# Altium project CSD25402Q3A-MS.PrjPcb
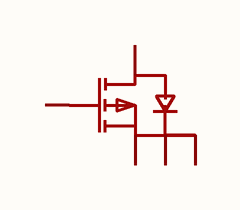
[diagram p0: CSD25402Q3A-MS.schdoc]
1 sheet, 1 parts. Net scope: global (net labels, ports and power ports of the same name join across sheets).

## Sheet CSD25402Q3A-MS.schdoc
size 127 x 101 mm

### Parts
Q?  csd25402q3a-ms  [DFN-8_L3.3-W3.3-P0.65-BL]  (value not drawn)

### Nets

Not connected (* = marked no-connect by the designer): Q? 1(S) 2(S) 3(S) 4(G) 5(D)

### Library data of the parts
Q? = csd25402q3a-ms: 数量:1个P沟道;漏源电压(Vdss):20V;连续漏极电流(Id):60A;导通电阻(RDS(on)):7mΩ@4.5V;耗散功率(Pd):22W;阈值电压(Vgs(th)):700mV;; Manufacturer: MSKSEMI(美森科); AddInBom: yes; ModelId: f0059a17dd8f409ba5a4c367eb8306e1; ModelTransform: 129.921,129.99974,0,0,0,0,0.002,31.498,0; Number: 1个P沟道; Drain to Source Voltage: 20V; Current - Continuous Drain(Id): 60A; Pd - Power Dissipation: 22W; Gate Threshold Voltage (Vgs(th)): 700mV; Gate Charge(Qg): 35nC; Input Capacitance(Ciss): 2.8nF; Reverse Transfer Capacitance (Crss@Vds): 590pF; Type: P沟道; Output Capacitance(Coss): 690pF; Vgs: ±12V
